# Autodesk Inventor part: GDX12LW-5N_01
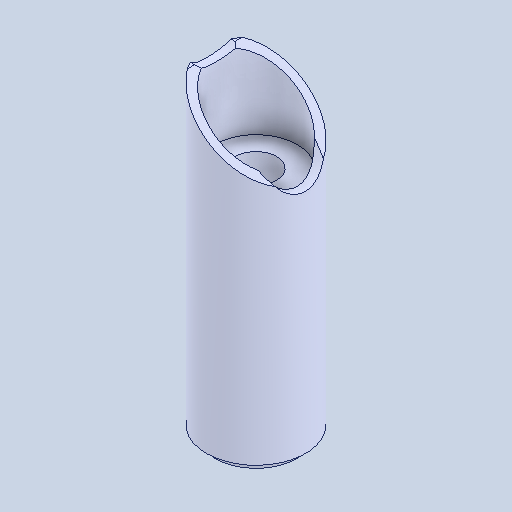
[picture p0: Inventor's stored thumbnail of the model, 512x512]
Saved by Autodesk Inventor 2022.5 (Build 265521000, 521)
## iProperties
Created: 2024-06
Part Number: GDX12LW-5N_01
Material: 一般
Document SubType Name: Modeling
Designer: ImaoCorp
Density: 1 g/cm^3
Appearance: 既定
Author: ImaoCorp
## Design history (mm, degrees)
feature "GDX12LW-5N_01"
node "ソリッド1"
